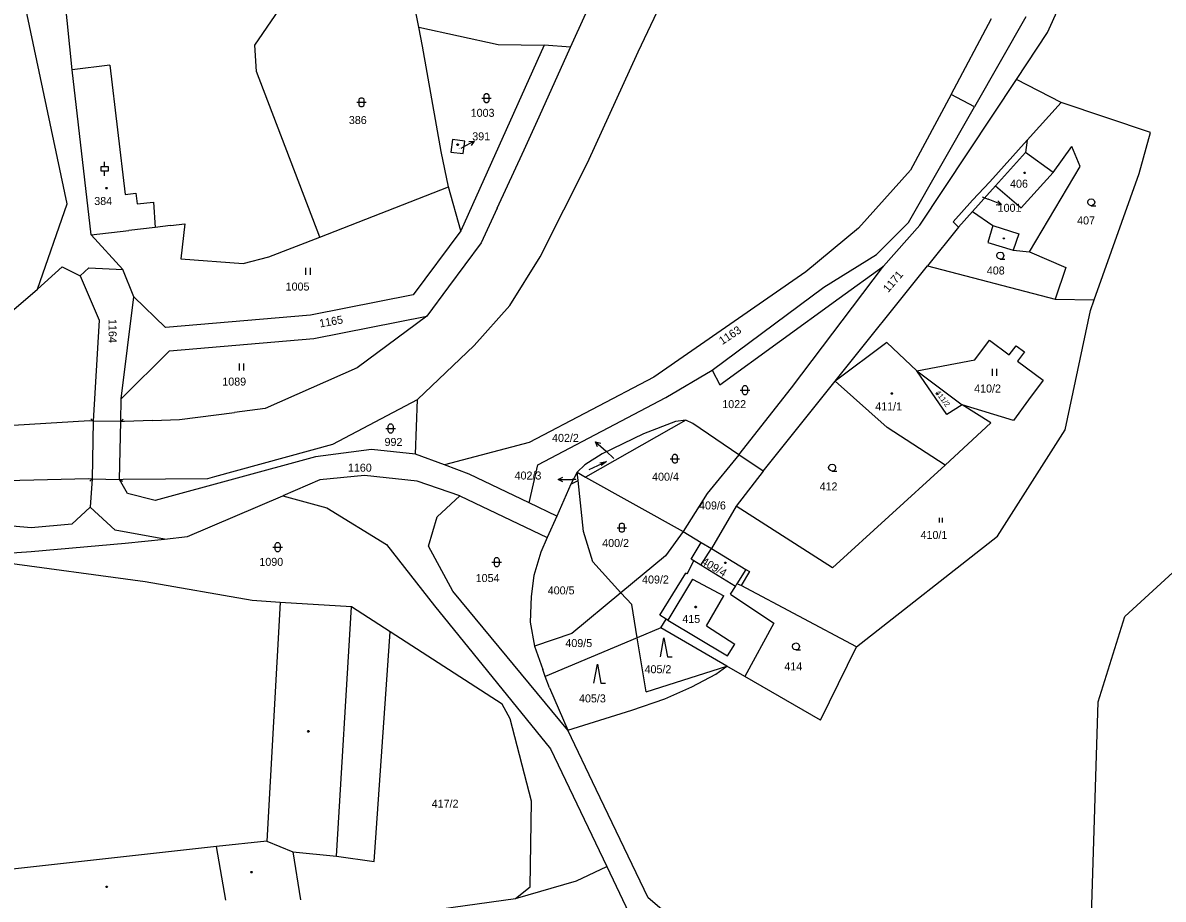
# Model space of a CAD drawing. Extents: x -812394 to -807601, y -1013097 to -1009266.
# Drawn here: x -810997.7 to -810755.5, y -1011724.6 to -1011538.5 of the extents above; entities that cross this region are included whole.
import ezdxf

# ---------------------------------------------------------------- set-up
doc = ezdxf.new("R2010")
doc.units = 0
for name, color, linetype in [('Default', 7, 'Continuous'), ('KN_HRANICE', 7, 'Continuous'), ('KN_KULTURY', 7, 'Continuous'), ('KN_PARCELY', 7, 'Continuous'), ('KN_SLUCKY', 7, 'Continuous')]:
    doc.layers.add(name, color=color, linetype=linetype)

# ---------------------------------------------------------------- blocks, each defined once
blk = doc.blocks.new('10292')
at = {"layer": 'Default'}
blk.add_line((0, 3), (0, 0), dxfattribs=at)
blk.add_lwpolyline([(-0.5, 2), (0, 3), (0.5, 2)], dxfattribs=at)
blk = doc.blocks.new('4201')
at = {"layer": 'Default'}
blk.add_line((0, 0), (-0.5, -0.5), dxfattribs=at)
blk = doc.blocks.new('304')
at = {"layer": 'Default'}
blk.add_lwpolyline([(0, 0), (-0.38, 0.1), (-0.65, 0.37), (-0.75, 0.74), (-0.65, 1.11), (-0.38, 1.38), (-0.01, 1.48), (0.36, 1.38), (0.63, 1.11), (0.73, 0.73), (0.63, 0.35), (0.36, 0.08), (-0.02, -0.02), (0.98, -0.02)], dxfattribs=at)
blk = doc.blocks.new('306')
at = {"layer": 'Default'}
for p, q in [((-0.5, 1.5), (-0.5, 0)), ((0.5, 0), (0.5, 1.5))]:
    blk.add_line(p, q, dxfattribs=at)
blk = doc.blocks.new('308')
at = {"layer": 'Default'}
blk.add_lwpolyline([(-0.75, 0), (0, 4), (0.75, 0), (1.75, 0)], dxfattribs=at)
blk = doc.blocks.new('316')
at = {"layer": 'Default'}
for points in [[(-1, 1), (0.27, 1), (1, 1)], [(-0.5, 1.5), (-0.4, 1.79), (-0.15, 1.97), (0.16, 1.97), (0.41, 1.79), (0.51, 1.5), (0.51, 0.5), (0.41, 0.21), (0.16, 0.03), (-0.15, 0.03), (-0.4, 0.21), (-0.5, 0.5), (-0.5, 1.5)]]:
    blk.add_lwpolyline(points, dxfattribs=at)
blk = doc.blocks.new('NAHRADNI_SYMBOL')
at = {"layer": 'Default'}
blk.add_lwpolyline([(0.09, 0.15), (0.18, 0), (0.09, -0.15), (-0.09, -0.15), (-0.18, 0), (-0.09, 0.15), (0.09, 0.15)], dxfattribs=at)
blk = doc.blocks.new('802')
at = {"layer": 'Default'}
blk.add_line((-3, 0), (3, 0), dxfattribs=at)
blk.add_lwpolyline([(1, 0.5), (3, 0), (1, -0.5)], dxfattribs=at)
blk = doc.blocks.new('318')
at = {"layer": 'Default'}
blk.add_line((0, 2), (0, 3), dxfattribs=at)
blk.add_lwpolyline([(0, 0), (0, 1), (-0.75, 1), (-0.75, 2), (0, 2), (0.75, 2), (0.75, 1), (0, 1)], dxfattribs=at)
blk = doc.blocks.new('402')
at = {"layer": 'Default'}
blk.add_lwpolyline([(0.09, 0.15), (0.18, 0), (0.09, -0.15), (-0.09, -0.15), (-0.18, 0), (-0.09, 0.15), (0.09, 0.15)], dxfattribs=at)

msp = doc.modelspace()

# ---------------------------------------------------------------- linework, layer by layer
at = {"layer": 'KN_HRANICE'}
for p, q in [((-810988.29, -1011576.92), (-811004.66, -1011499.57)), ((-810913.6, -1011539.41), (-810916.42, -1011525.41)), ((-810987.2, -1011548.48), (-810988.82, -1011532.52)), ((-810948.4, -1011543.24), (-810941.47, -1011533.07)), ((-810881.34, -1011543.7), (-810878.11, -1011536.55)), ((-810800.53, -1011553.7), (-810791.91, -1011537.6)), ((-810784.63, -1011537.23), (-810795.57, -1011556.36)), ((-810913.6, -1011539.41), (-810896.75, -1011543.11)), ((-810912.78, -1011543.48), (-810913.6, -1011539.41)), ((-810896.75, -1011543.11), (-810886.95, -1011543.28)), ((-810948.04, -1011548.87), (-810948.4, -1011543.24)), ((-810908.81, -1011565.82), (-810912.78, -1011543.48)), ((-810886.95, -1011543.28), (-810904.65, -1011582.69)), ((-810888.01, -1011558.44), (-810881.34, -1011543.7)), ((-810881.34, -1011543.7), (-810886.95, -1011543.28)), ((-810983.14, -1011583.56), (-810987.2, -1011548.48)), ((-810934.61, -1011584.01), (-810948.04, -1011548.87)), ((-810777.16, -1011555.46), (-810786.65, -1011550.55)), ((-810800.53, -1011553.7), (-810809.15, -1011569.79)), ((-810795.57, -1011556.36), (-810800.53, -1011553.7)), ((-810809.59, -1011580.88), (-810795.57, -1011556.36)), ((-810777.16, -1011555.46), (-810784.33, -1011563.43)), ((-810758.13, -1011561.79), (-810777.16, -1011555.46)), ((-810760.56, -1011570.51), (-810758.13, -1011561.79)), ((-810784.33, -1011563.43), (-810784.69, -1011566.07)), ((-810778.84, -1011570.27), (-810774.83, -1011564.74)), ((-810773.09, -1011568.99), (-810774.83, -1011564.74)), ((-810907.28, -1011573.34), (-810908.81, -1011565.82)), ((-810784.69, -1011566.07), (-810791.05, -1011573.12)), ((-810778.84, -1011570.27), (-810784.69, -1011566.07)), ((-810783.83, -1011587.16), (-810773.09, -1011568.99)), ((-810809.15, -1011569.79), (-810820.21, -1011582.08)), ((-810770.11, -1011597.34), (-810760.56, -1011570.51)), ((-810934.61, -1011584.01), (-810907.28, -1011573.34)), ((-810904.65, -1011582.69), (-810907.28, -1011573.34)), ((-810791.05, -1011573.12), (-810795.98, -1011578.6)), ((-810994.59, -1011595.07), (-810988.29, -1011576.92)), ((-810896.93, -1011577.89), (-810900.33, -1011585.26)), ((-810795.98, -1011578.6), (-810798.92, -1011581.87)), ((-810795.98, -1011578.6), (-810791.67, -1011581.54)), ((-810966.35, -1011581.58), (-810969.54, -1011581.95)), ((-810966.35, -1011581.58), (-810963.27, -1011581.22)), ((-810963.27, -1011581.22), (-810964.13, -1011588.63)), ((-810816.35, -1011587.73), (-810809.59, -1011580.88)), ((-810798.92, -1011581.87), (-810805.49, -1011590.1)), ((-810791.67, -1011581.54), (-810792.74, -1011585.15)), ((-810983.14, -1011583.56), (-810975.16, -1011582.61)), ((-810976.41, -1011590.91), (-810983.14, -1011583.56)), ((-810969.54, -1011581.95), (-810975.16, -1011582.61)), ((-810945.41, -1011588.22), (-810934.61, -1011584.01)), ((-810904.65, -1011582.69), (-810914.75, -1011596.26)), ((-810820.21, -1011582.08), (-810831.4, -1011591.35)), ((-810900.33, -1011585.26), (-810907.25, -1011594.56)), ((-810792.74, -1011585.15), (-810787.3, -1011586.77)), ((-810964.13, -1011588.63), (-810950.86, -1011589.65)), ((-810950.86, -1011589.65), (-810945.41, -1011588.22)), ((-810827.53, -1011594.64), (-810816.35, -1011587.73)), ((-810787.3, -1011586.77), (-810783.83, -1011587.16)), ((-810783.83, -1011587.16), (-810776.13, -1011590.43)), ((-810994.59, -1011595.07), (-810989.3, -1011590.32)), ((-810989.3, -1011590.32), (-810985.49, -1011592.2)), ((-810985.49, -1011592.2), (-810983.65, -1011590.57)), ((-810983.65, -1011590.57), (-810976.41, -1011590.91)), ((-810974.14, -1011596.72), (-810976.41, -1011590.91)), ((-810831.4, -1011591.35), (-810863.67, -1011613.78)), ((-810825.11, -1011614.6), (-810805.49, -1011590.1)), ((-810824.29, -1011596.97), (-810814.84, -1011590.15)), ((-810805.49, -1011590.1), (-810778.39, -1011597.16)), ((-810776.13, -1011590.43), (-810778.39, -1011597.16)), ((-810985.49, -1011592.2), (-810981.49, -1011601.67)), ((-811020.14, -1011616.85), (-810994.59, -1011595.07)), ((-810914.75, -1011596.26), (-810936.59, -1011600.58)), ((-810907.25, -1011594.56), (-810911.89, -1011600.79)), ((-810851.23, -1011612.3), (-810827.53, -1011594.64)), ((-810976.79, -1011618.38), (-810974.14, -1011596.72)), ((-810967.38, -1011603.18), (-810974.14, -1011596.72)), ((-810849.63, -1011615.36), (-810824.29, -1011596.97)), ((-810778.39, -1011597.16), (-810770.11, -1011597.34)), ((-810770.92, -1011599.62), (-810770.11, -1011597.34)), ((-810936.59, -1011600.58), (-810967.38, -1011603.18)), ((-810935.89, -1011605.54), (-810911.89, -1011600.79)), ((-810776.29, -1011624.93), (-810770.92, -1011599.62)), ((-810981.49, -1011601.67), (-810982.75, -1011623.07)), ((-810966.54, -1011608.13), (-810935.89, -1011605.54)), ((-810795.48, -1011610.09), (-810792.38, -1011605.92)), ((-810792.38, -1011605.92), (-810788.17, -1011609.04)), ((-810976.79, -1011618.38), (-810966.54, -1011608.13)), ((-810814.15, -1011606.38), (-810825.11, -1011614.6)), ((-810807.8, -1011612.43), (-810814.15, -1011606.38)), ((-810788.17, -1011609.04), (-810786.71, -1011607.08)), ((-810786.71, -1011607.08), (-810784.94, -1011608.39)), ((-810784.94, -1011608.39), (-810786.4, -1011610.35)), ((-810807.8, -1011612.43), (-810795.48, -1011610.09)), ((-810786.4, -1011610.35), (-810780.94, -1011614.41)), ((-810861.07, -1011618.06), (-810851.23, -1011612.3)), ((-810851.23, -1011612.3), (-810849.63, -1011615.36)), ((-810801.41, -1011621.68), (-810807.8, -1011612.43)), ((-810807.8, -1011612.43), (-810798.15, -1011619.6)), ((-810863.67, -1011613.78), (-810890.13, -1011627.65)), ((-810840.43, -1011633.72), (-810825.11, -1011614.6)), ((-810814.09, -1011624.47), (-810825.11, -1011614.6)), ((-810780.94, -1011614.41), (-810784.04, -1011618.58)), ((-810888.31, -1011632.34), (-810861.07, -1011618.06)), ((-810976.85, -1011623.16), (-810976.79, -1011618.38)), ((-810914.28, -1011630.13), (-810913.82, -1011618.49)), ((-810798.15, -1011619.6), (-810801.41, -1011621.68)), ((-810787.28, -1011622.93), (-810798.15, -1011619.6)), ((-810792.08, -1011623.48), (-810798.15, -1011619.6)), ((-810784.04, -1011618.58), (-810787.28, -1011622.93)), ((-810976.85, -1011623.16), (-810982.75, -1011623.07)), ((-810856.83, -1011622.91), (-810878.14, -1011634.96)), ((-810856.83, -1011622.91), (-810859.07, -1011623.17)), ((-810855.38, -1011623.6), (-810856.83, -1011622.91)), ((-810859.07, -1011623.17), (-810865.83, -1011625.76)), ((-810845.57, -1011630.24), (-810855.38, -1011623.6)), ((-810801.74, -1011632.47), (-810814.09, -1011624.47)), ((-810792.08, -1011623.48), (-810801.74, -1011632.47)), ((-810790.62, -1011647.55), (-810776.29, -1011624.93)), ((-810890.13, -1011627.65), (-810908.12, -1011632.39)), ((-810865.83, -1011625.76), (-810874.64, -1011630.05)), ((-810923.64, -1011629.14), (-810935.55, -1011630.66)), ((-810914.28, -1011630.13), (-810923.64, -1011629.14)), ((-810908.12, -1011632.39), (-810914.28, -1011630.13)), ((-810874.64, -1011630.05), (-810878.34, -1011632.37)), ((-810845.57, -1011630.24), (-810852.3, -1011638.43)), ((-810840.43, -1011633.72), (-810845.57, -1011630.24)), ((-810935.55, -1011630.66), (-810969.6, -1011639.97)), ((-810902.89, -1011634.32), (-810908.12, -1011632.39)), ((-810890.13, -1011640.47), (-810888.31, -1011632.34)), ((-810878.34, -1011632.37), (-810879.94, -1011633.96)), ((-810801.74, -1011632.47), (-810825.68, -1011654.24)), ((-810925.1, -1011634.66), (-810934.57, -1011635.58)), ((-810913.89, -1011635.85), (-810925.1, -1011634.66)), ((-810890.13, -1011640.47), (-810902.89, -1011634.32)), ((-810879.94, -1011633.96), (-810881.3, -1011636.47)), ((-810879.75, -1011635.73), (-810879.94, -1011633.96)), ((-810879.94, -1011633.96), (-810878.14, -1011634.96)), ((-810878.14, -1011634.96), (-810857.44, -1011646.51)), ((-810840.43, -1011633.72), (-810846.16, -1011641.14)), ((-810982.94, -1011635.34), (-810983.35, -1011641.36)), ((-810982.94, -1011635.34), (-810977.14, -1011635.5)), ((-810975.48, -1011638.44), (-810977.14, -1011635.5)), ((-810934.57, -1011635.58), (-810942.44, -1011638.95)), ((-810904.85, -1011638.92), (-810913.89, -1011635.85)), ((-810881.3, -1011636.47), (-810884.27, -1011643.3)), ((-810881.3, -1011636.47), (-810879.75, -1011635.73)), ((-810878.58, -1011646.5), (-810879.75, -1011635.73)), ((-810969.6, -1011639.97), (-810975.48, -1011638.44)), ((-810962.69, -1011647.62), (-810942.44, -1011638.95)), ((-810942.44, -1011638.95), (-810933.12, -1011641.48)), ((-810909.69, -1011643.43), (-810904.85, -1011638.92)), ((-810904.85, -1011638.92), (-810886.34, -1011647.79)), ((-810852.3, -1011638.43), (-810857.44, -1011646.51)), ((-810983.35, -1011641.36), (-810987.28, -1011645)), ((-810978.06, -1011646.24), (-810983.35, -1011641.36)), ((-810933.12, -1011641.48), (-810920.45, -1011649.26)), ((-810884.27, -1011643.3), (-810890.13, -1011640.47)), ((-810846.16, -1011641.14), (-810851.41, -1011650.14)), ((-810825.68, -1011654.24), (-810846.16, -1011641.14)), ((-810995.89, -1011645.77), (-811016.44, -1011643.9)), ((-810911.51, -1011649.61), (-810909.69, -1011643.43)), ((-810884.27, -1011643.3), (-810886.34, -1011647.79)), ((-810987.28, -1011645), (-810995.89, -1011645.77)), ((-810967.59, -1011648.15), (-810978.06, -1011646.24)), ((-810876.64, -1011652.99), (-810878.58, -1011646.5)), ((-810857.44, -1011646.51), (-810861.19, -1011651.67)), ((-810857.44, -1011646.51), (-810853.61, -1011648.83)), ((-810995.89, -1011650.79), (-810975.92, -1011649.01)), ((-810975.92, -1011649.01), (-810967.59, -1011648.15)), ((-810967.59, -1011648.15), (-810962.69, -1011647.62)), ((-810920.45, -1011649.26), (-810910.24, -1011662.33)), ((-810906.32, -1011659.22), (-810911.51, -1011649.61)), ((-810886.34, -1011647.79), (-810887.64, -1011650.91)), ((-810855.74, -1011652.37), (-810853.61, -1011648.83)), ((-810853.61, -1011648.83), (-810851.41, -1011650.14)), ((-810820.6, -1011671.03), (-810790.62, -1011647.55)), ((-811011.38, -1011651.85), (-810995.89, -1011650.79)), ((-810971.7, -1011657.24), (-811011.38, -1011651.85)), ((-810887.64, -1011650.91), (-810889.14, -1011655.88)), ((-810861.19, -1011651.67), (-810870.64, -1011659.53)), ((-810851.41, -1011650.14), (-810844.12, -1011654.56)), ((-810763.59, -1011664.59), (-810749.89, -1011651.97)), ((-810870.64, -1011659.53), (-810876.64, -1011652.99)), ((-810856.54, -1011655.55), (-810855.16, -1011652.74)), ((-810855.16, -1011652.74), (-810855.74, -1011652.37)), ((-810853.65, -1011653.71), (-810855.16, -1011652.74)), ((-810846.33, -1011658.17), (-810853.65, -1011653.71)), ((-810844.12, -1011654.56), (-810843.35, -1011655.03)), ((-810889.14, -1011655.88), (-810889.71, -1011660.31)), ((-810862.38, -1011664.26), (-810856.89, -1011655.34)), ((-810856.54, -1011655.55), (-810856.89, -1011655.34)), ((-810843.35, -1011655.03), (-810845.13, -1011657.96)), ((-810948.98, -1011661.21), (-810971.7, -1011657.24)), ((-810881.94, -1011688.74), (-810906.32, -1011659.22)), ((-810847.39, -1011659.86), (-810846.33, -1011658.17)), ((-810846.33, -1011658.17), (-810846.01, -1011657.66)), ((-810845.13, -1011657.96), (-810846.01, -1011657.66)), ((-810820.6, -1011671.03), (-810845.13, -1011657.96)), ((-810943.04, -1011661.57), (-810948.98, -1011661.21)), ((-810927.88, -1011662.52), (-810943.04, -1011661.57)), ((-810889.71, -1011660.31), (-810889.93, -1011665.8)), ((-810870.64, -1011659.53), (-810881.07, -1011668.21)), ((-810868.35, -1011662.02), (-810870.64, -1011659.53)), ((-810847.39, -1011659.86), (-810838.13, -1011666.01)), ((-810919.67, -1011667.84), (-810927.88, -1011662.52)), ((-810910.24, -1011662.33), (-810885.61, -1011692.65)), ((-810867.17, -1011669.11), (-810868.35, -1011662.02)), ((-810889.93, -1011665.8), (-810888.97, -1011670.87)), ((-810861.06, -1011665.11), (-810862.38, -1011664.26)), ((-810862.16, -1011667.01), (-810861.06, -1011665.11)), ((-810838.13, -1011666.01), (-810844.35, -1011677.34)), ((-810769.26, -1011682.72), (-810763.59, -1011664.59)), ((-810923.04, -1011716.62), (-810919.67, -1011667.84)), ((-810895.87, -1011683.21), (-810919.67, -1011667.84)), ((-810881.07, -1011668.21), (-810888.97, -1011670.87)), ((-810862.16, -1011667.01), (-810867.17, -1011669.11)), ((-810848.18, -1011675.13), (-810862.16, -1011667.01)), ((-810888.97, -1011670.87), (-810887.26, -1011675.84)), ((-810867.17, -1011669.11), (-810886.7, -1011677.32)), ((-810865.26, -1011680.6), (-810867.17, -1011669.11)), ((-810828.27, -1011686.59), (-810820.6, -1011671.03)), ((-810886.7, -1011677.32), (-810887.26, -1011675.84)), ((-810865.26, -1011680.6), (-810848.18, -1011675.13)), ((-810850.5, -1011676.82), (-810848.18, -1011675.13)), ((-810844.35, -1011677.34), (-810848.18, -1011675.13)), ((-810885.79, -1011679.69), (-810886.7, -1011677.32)), ((-810855.6, -1011679.52), (-810850.5, -1011676.82)), ((-810828.27, -1011686.59), (-810844.35, -1011677.34)), ((-810885.79, -1011679.69), (-810881.94, -1011688.74)), ((-810861.34, -1011682.08), (-810855.6, -1011679.52)), ((-810894.15, -1011686.31), (-810895.87, -1011683.21)), ((-810868.35, -1011684.5), (-810861.34, -1011682.08)), ((-810770.67, -1011728.15), (-810769.26, -1011682.72)), ((-810881.94, -1011688.74), (-810868.35, -1011684.5)), ((-810889.63, -1011703.76), (-810894.15, -1011686.31)), ((-810875.9, -1011701.34), (-810881.94, -1011688.74)), ((-810885.61, -1011692.65), (-810873.63, -1011717.68)), ((-810864.89, -1011724.35), (-810875.9, -1011701.34)), ((-810889.92, -1011721.98), (-810889.63, -1011703.76)), ((-810940.3, -1011714.57), (-810931.06, -1011715.46)), ((-810940.3, -1011714.57), (-810938.7, -1011724.76)), ((-810931.06, -1011715.46), (-810923.04, -1011716.62)), ((-810880.1, -1011720.69), (-810873.63, -1011717.68)), ((-810873.63, -1011717.68), (-810868.94, -1011727.48)), ((-810893.06, -1011724.45), (-810880.1, -1011720.69)), ((-810893.06, -1011724.45), (-810889.92, -1011721.98)), ((-810920.02, -1011728.18), (-810893.06, -1011724.45)), ((-810846.21, -1011740.05), (-810864.89, -1011724.35))]:
    msp.add_line(p, q, dxfattribs=at)
for points in [[(-810887.79, -1011588.2), (-810877.76, -1011568.21), (-810866.95, -1011544.7), (-810857.48, -1011524.61), (-810845.94, -1011498.21), (-810817.11, -1011436.78)], [(-810786.65, -1011550.55), (-810780.03, -1011540.57), (-810775.59, -1011530.62), (-810772.3, -1011515.42), (-810772.06, -1011507.46), (-810775.87, -1011475.3)], [(-810814.84, -1011590.15), (-810807.13, -1011581.45), (-810786.65, -1011550.55)], [(-810896.93, -1011577.89), (-810891.18, -1011565.46), (-810888.01, -1011558.44)], [(-810784.33, -1011563.43), (-810792.3, -1011572.28), (-810795.98, -1011576.16), (-810800.04, -1011580.78), (-810798.92, -1011581.87)], [(-810913.82, -1011618.49), (-810901.8, -1011607.05), (-810894.25, -1011598.54), (-810887.79, -1011588.2)], [(-810845.57, -1011630.24), (-810834.41, -1011616.01), (-810814.84, -1011590.15)], [(-810911.89, -1011600.79), (-810926.65, -1011611.75), (-810946.18, -1011620.4), (-810952.71, -1011621.24)], [(-810956.88, -1011634.82), (-810931.83, -1011627.95), (-810913.82, -1011618.49)], [(-810982.75, -1011623.07), (-810983.49, -1011623.04), (-811005.6, -1011624.4)], [(-810970.17, -1011622.97), (-810976.1, -1011623.19), (-810976.85, -1011623.16)], [(-810970.17, -1011622.97), (-810964.43, -1011622.75), (-810952.71, -1011621.24)], [(-810977.14, -1011635.5), (-810976.39, -1011635.39), (-810958.42, -1011635.24), (-810956.88, -1011634.82)], [(-811029.29, -1011645.78), (-811020.71, -1011639.62), (-811010, -1011635.94), (-810983.72, -1011635.29), (-810982.94, -1011635.34)]]:
    msp.add_lwpolyline(points, dxfattribs=at)
msp.add_lwpolyline([(-810906.8, -1011565.95), (-810904.15, -1011566.29), (-810903.81, -1011563.64), (-810906.45, -1011563.25)], close=True, dxfattribs=at)
at = {"layer": 'KN_PARCELY'}
for p, q in [((-810904.55, -1011565.14), (-810904.44, -1011565.08)), ((-810793.9, -1011575.45), (-810792.61, -1011575.98)), ((-810872.12, -1011630.99), (-810873.78, -1011629.5)), ((-810880.24, -1011635.49), (-810880.98, -1011635.49))]:
    msp.add_line(p, q, dxfattribs=at)
at = {"layer": 'KN_SLUCKY'}
for p, q in [((-810979.2, -1011547.53), (-810987.2, -1011548.48)), ((-810979.2, -1011547.53), (-810975.94, -1011574.98)), ((-810785.63, -1011577.82), (-810778.84, -1011570.27)), ((-810791.05, -1011573.12), (-810785.63, -1011577.82)), ((-810975.94, -1011574.98), (-810973.66, -1011574.71)), ((-810973.66, -1011574.71), (-810973.39, -1011576.98)), ((-810973.39, -1011576.98), (-810969.94, -1011576.57)), ((-810969.94, -1011576.57), (-810969.54, -1011581.95)), ((-810791.67, -1011581.54), (-810786.13, -1011583.33)), ((-810786.13, -1011583.33), (-810787.3, -1011586.77)), ((-810982.75, -1011623.07), (-810982.94, -1011635.34)), ((-810977.14, -1011635.5), (-810976.85, -1011623.16)), ((-810853.65, -1011653.71), (-810851.41, -1011650.14)), ((-810844.12, -1011654.56), (-810846.01, -1011657.66)), ((-810855.41, -1011656.64), (-810860.65, -1011665.37)), ((-810855.41, -1011656.64), (-810848.77, -1011660.2)), ((-810943.04, -1011661.57), (-810945.82, -1011712.25)), ((-810852.43, -1011666.59), (-810848.77, -1011660.2)), ((-810931.06, -1011715.46), (-810927.88, -1011662.52)), ((-810860.65, -1011665.37), (-810861.06, -1011665.11)), ((-810860.65, -1011665.37), (-810848.03, -1011672.95)), ((-810852.43, -1011666.59), (-810846.42, -1011670.43)), ((-810848.03, -1011672.95), (-810846.42, -1011670.43)), ((-810945.82, -1011712.25), (-810956.56, -1011713.43)), ((-810945.82, -1011712.25), (-810940.3, -1011714.57)), ((-810956.56, -1011713.43), (-811006.65, -1011718.94)), ((-810954.56, -1011724.79), (-810956.56, -1011713.43))]:
    msp.add_line(p, q, dxfattribs=at)

# ---------------------------------------------------------------- block references
at = {"layer": 'KN_KULTURY'}
for name, p in [('316', (-810925.75, -1011556.38)), ('316', (-810899.19, -1011555.5)), ('402', (-810905.32, -1011564.38)), ('318', (-810980.31, -1011571.03)), ('402', (-810784.91, -1011570.35)), ('402', (-810979.91, -1011573.6)), ('304', (-810770.73, -1011577.34)), ('304', (-810790.05, -1011588.67)), ('306', (-810937.11, -1011592.02)), ('306', (-810951.22, -1011612.37)), ('306', (-810791.28, -1011613.49)), ('316', (-810844.29, -1011617.5)), ('NAHRADNI_SYMBOL', (-810813.1, -1011617.23)), ('316', (-810919.55, -1011625.66)), ('316', (-810859.18, -1011632.08)), ('304', (-810825.78, -1011633.7)), ('316', (-810870.44, -1011646.72)), ('316', (-810943.55, -1011650.85)), ('316', (-810897.03, -1011654.03)), ('402', (-810848.46, -1011653.19)), ('402', (-810854.78, -1011662.56)), ('308', (-810861.51, -1011673.14)), ('304', (-810833.45, -1011671.66)), ('308', (-810875.65, -1011678.71)), ('402', (-810937.02, -1011688.96)), ('402', (-810949.11, -1011718.86)), ('402', (-810979.87, -1011721.99))]:
    msp.add_blockref(name, p, dxfattribs=at)
at = {"layer": 'KN_KULTURY', "xscale": 0.67, "yscale": 0.67}
for name, p in [('402', (-810789.32, -1011584.29)), ('NAHRADNI_SYMBOL', (-810803.56, -1011617.27)), ('306', (-810802.7, -1011644.63))]:
    msp.add_blockref(name, p, dxfattribs=at)
at = {"layer": 'KN_KULTURY', "xscale": 0.67, "yscale": 0.67, "rotation": 24.637185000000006}
msp.add_blockref('802', (-810875.56, -1011632.52), dxfattribs=at)
at = {"layer": 'KN_PARCELY'}
for p, rotation in [((-810904.44, -1011565.08), -61.71817200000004), ((-810792.61, -1011575.98), -112.25304900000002), ((-810873.78, -1011629.5), 48.185750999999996), ((-810880.98, -1011635.49), 90.01166999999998)]:
    msp.add_blockref('10292', p, dxfattribs=dict(at, rotation=rotation))
at = {"layer": 'KN_SLUCKY'}
for p, rotation in [((-810982.75, -1011623.07), -90.07958300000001), ((-810976.85, -1011623.16), -178.02860400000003), ((-810977.14, -1011635.5), 105.53882599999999)]:
    msp.add_blockref('4201', p, dxfattribs=dict(at, rotation=rotation))
msp.add_blockref('4201', (-810982.94, -1011635.34), dxfattribs=at)

# ---------------------------------------------------------------- texts
at = {"layer": 'KN_PARCELY'}
for s, height, p in [('1003', 1.7, (-810902.55, -1011558.47)), ('386', 1.7, (-810928.43, -1011560)), ('391', 1.7, (-810902.22, -1011563.46)), ('391', 0.1, (-810905.12, -1011565.29)), ('406', 1.7, (-810787.98, -1011573.52)), ('384', 1.7, (-810982.51, -1011577.19)), ('1001', 1.7, (-810790.62, -1011578.64)), ('407', 1.7, (-810773.74, -1011581.32)), ('408', 1.7, (-810792.92, -1011591.95)), ('1005', 1.7, (-810941.86, -1011595.36)), ('1089', 1.7, (-810955.31, -1011615.54)), ('410/2', 1.7, (-810795.61, -1011617.01)), ('1022', 1.7, (-810849.11, -1011620.33)), ('411/1', 1.7, (-810816.62, -1011620.81)), ('992', 1.7, (-810920.85, -1011628.36)), ('402/2', 1.7, (-810885.27, -1011627.5)), ('1160', 1.7, (-810928.63, -1011633.82)), ('402/2', 0.1, (-810872.36, -1011630.99)), ('402/3', 1.7, (-810893.23, -1011635.49)), ('400/4', 1.7, (-810864.02, -1011635.74)), ('402/3', 0.1, (-810880.48, -1011635.49)), ('412', 1.7, (-810828.44, -1011637.81)), ('409/6', 1.7, (-810854.04, -1011641.84)), ('410/1', 1.7, (-810807, -1011648.11)), ('400/2', 1.7, (-810874.62, -1011649.82)), ('1090', 1.7, (-810947.44, -1011653.82)), ('1054', 1.7, (-810901.49, -1011657.26)), ('409/2', 1.7, (-810866.15, -1011657.57)), ('400/5', 1.7, (-810886.18, -1011659.88)), ('415', 1.7, (-810857.61, -1011665.95)), ('409/5', 1.7, (-810882.44, -1011671.07)), ('405/2', 1.7, (-810865.62, -1011676.62)), ('414', 1.7, (-810835.93, -1011676.02)), ('405/3', 1.7, (-810879.54, -1011682.82)), ('417/2', 1.7, (-810910.83, -1011705.17))]:
    msp.add_text(s, height=height, dxfattribs=at).set_placement(p)
for s, height, rotation, p in [('1001', 0.1, 49.217, (-810795.57, -1011577.52)), ('1171', 1.7, 49.389, (-810813.86, -1011595.89)), ('1165', 1.7, 10.313, (-810934.54, -1011603.21)), ('1164', 1.7, 269.978, (-810979.46, -1011601.41)), ('1163', 1.7, 33.403, (-810849.12, -1011606.95)), ('411/2', 1.14, 307.22, (-810803.92, -1011617.08)), ('409/4', 1.7, 329.279, (-810853.7, -1011653.35))]:
    msp.add_text(s, height=height, rotation=rotation, dxfattribs=at).set_placement(p)

doc.saveas('drawing.dxf')
